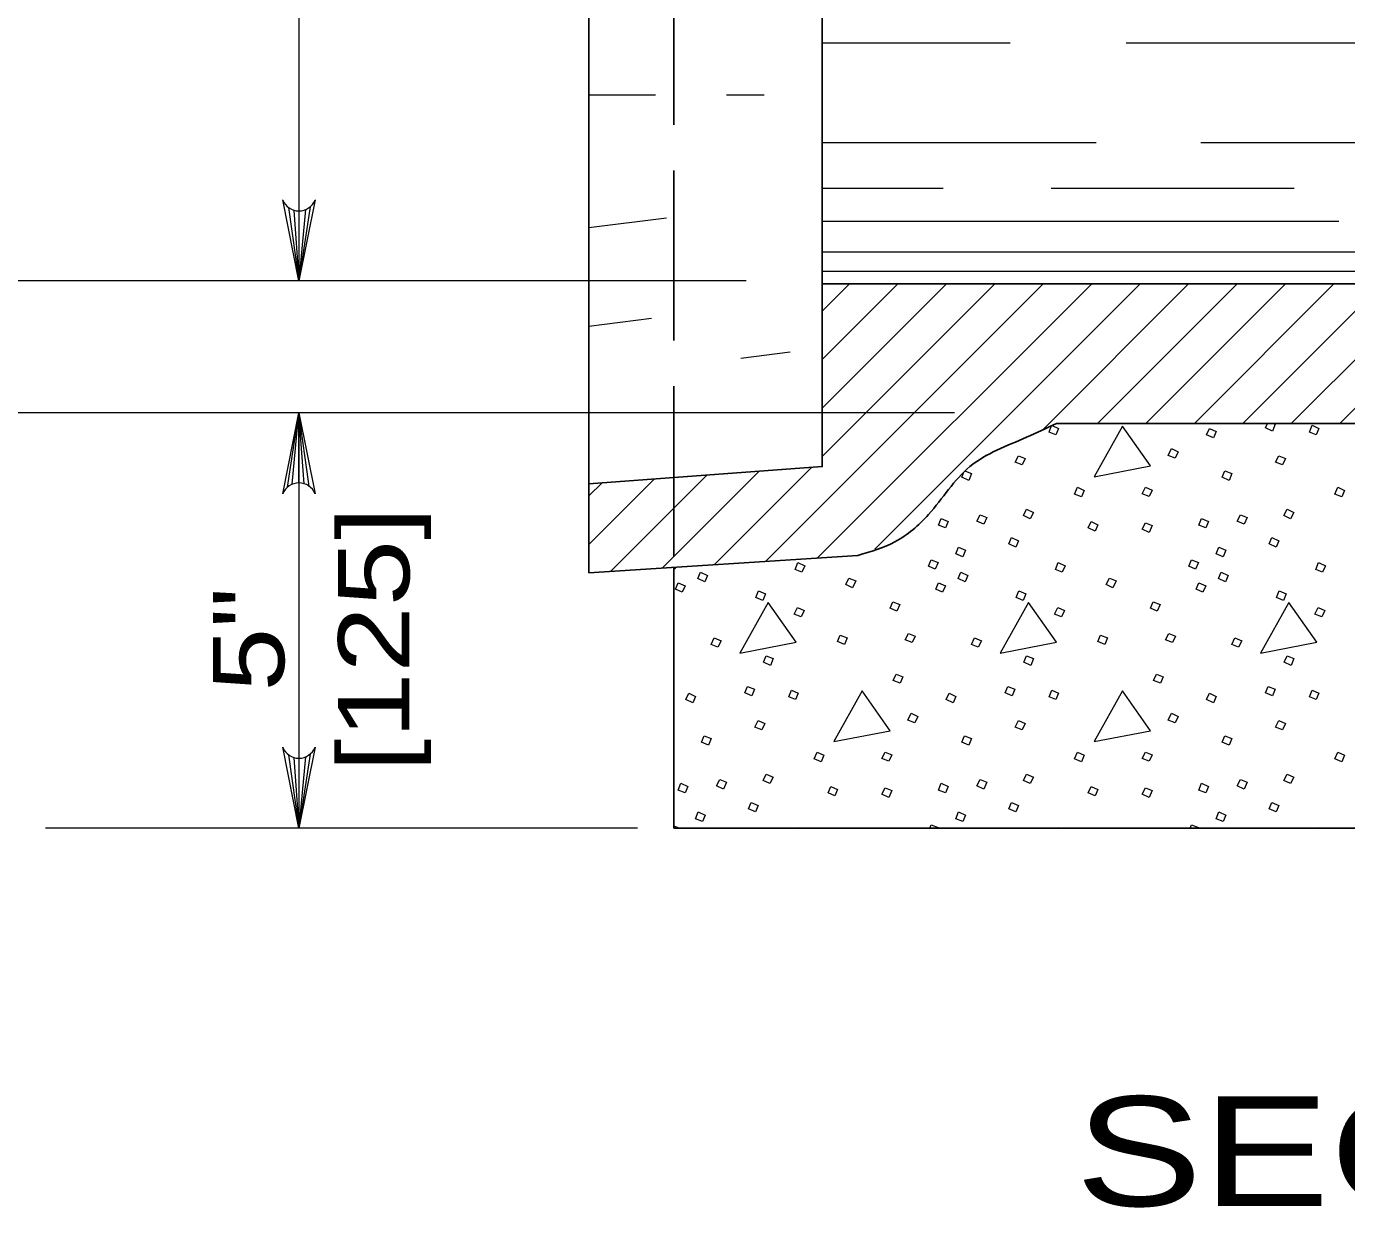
# Model space of a CAD drawing. Extents: x 1036.7 to 1070.7, y 883.9 to 905.9.
# Drawn here: x 1056.851 to 1059.74, y 892.979 to 895.565 of the extents above; entities that cross this region are included whole.
import ezdxf
from ezdxf.enums import TextEntityAlignment as Align

# ---------------------------------------------------------------- set-up
doc = ezdxf.new("R2010")
doc.units = 0
doc.header["$LTSCALE"] = 0.062
doc.linetypes.add('LONG_DASHED', pattern=[7.5, 6, -1.5])
doc.layers.add('1', color=7, linetype='Continuous', lineweight=13)

msp = doc.modelspace()

# ---------------------------------------------------------------- linework, layer by layer
at = {"layer": '1', "lineweight": 25}
for p, q in [((1058.08233, 898.76567), (1058.08233, 894.5635)), ((1058.59283, 898.16642), (1058.59283, 894.9815)), ((1062.80458, 895.00108), (1058.59283, 895.00108)), ((1062.80458, 894.69575), (1059.10533, 894.69575)), ((1058.67108, 894.407), (1058.08233, 894.36883)), ((1058.26842, 894.38092), (1058.26842, 893.80992))]:
    msp.add_line(p, q, dxfattribs=at)
at = {"layer": '1', "linetype": 'LONG_DASHED', "lineweight": 25}
msp.add_line((1058.26842, 898.55342), (1058.26842, 894.38092), dxfattribs=at)
at = {"layer": '1'}
for p, q in [((1057.4475, 895.8775), (1057.4475, 895.00783)), ((1058.59283, 895.52883), (1059.00425, 895.52883)), ((1059.25767, 895.52883), (1059.82158, 895.52883)), ((1058.08233, 895.41525), (1058.228, 895.41525)), ((1058.383, 895.41525), (1058.46592, 895.41525)), ((1058.59283, 895.31058), (1059.19225, 895.31058)), ((1059.42108, 895.31058), (1060.05858, 895.31058)), ((1058.59283, 895.21083), (1058.85717, 895.21083)), ((1059.09417, 895.21083), (1059.62542, 895.21083)), ((1057.42508, 895.168), (1057.4475, 895.00783)), ((1057.43617, 895.16258), (1057.4475, 895.00783)), ((1057.47225, 895.16992), (1057.4475, 895.00783)), ((1057.46192, 895.16383), (1057.4475, 895.00783)), ((1057.4475, 895.161), (1057.4475, 895.00783)), ((1058.08233, 895.12425), (1058.25175, 895.14592)), ((1058.59283, 895.13858), (1059.7235, 895.13858)), ((1058.59283, 895.07167), (1062.80458, 895.07167)), ((1058.42608, 895.00783), (1054.42967, 895.00783)), ((1058.59283, 895.029), (1062.80458, 895.029)), ((1058.46933, 894.39392), (1059.07658, 895.00108)), ((1058.58275, 894.40125), (1059.18258, 895.00108)), ((1058.59283, 894.94133), (1058.6525, 895.00108)), ((1058.59283, 894.83533), (1058.75858, 895.00108)), ((1058.59283, 894.72942), (1058.8645, 895.00108)), ((1058.59283, 894.62333), (1058.97058, 895.00108)), ((1058.708, 894.4205), (1059.28867, 895.00108)), ((1059.07542, 894.68192), (1059.39458, 895.00108)), ((1059.19525, 894.69575), (1059.50067, 895.00108)), ((1059.30133, 894.69575), (1059.60667, 895.00108)), ((1059.40733, 894.69575), (1059.71267, 895.00108)), ((1059.51333, 894.69575), (1059.81875, 895.00108)), ((1059.61933, 894.69575), (1059.92467, 895.00108)), ((1059.72533, 894.69575), (1060.03075, 895.00108)), ((1058.08233, 894.90883), (1058.21942, 894.92633)), ((1058.4145, 894.83842), (1058.52233, 894.85217)), ((1058.88267, 894.71867), (1054.302, 894.71867)), ((1057.42275, 894.5565), (1057.4475, 894.71867)), ((1057.43308, 894.56267), (1057.4475, 894.71867)), ((1057.4475, 894.5655), (1057.4475, 894.71867)), ((1057.45883, 894.56383), (1057.4475, 894.71867)), ((1057.46992, 894.55842), (1057.4475, 894.71867)), ((1058.08233, 894.43092), (1058.22558, 894.57417)), ((1058.12925, 894.37192), (1058.34, 894.58267)), ((1058.24267, 894.37925), (1058.4545, 894.59108)), ((1058.356, 894.38658), (1058.56908, 894.59958)), ((1058.08233, 894.53692), (1058.111, 894.56567)), ((1058.08233, 894.36883), (1058.26842, 894.38092)), ((1057.42508, 893.97017), (1057.4475, 893.80992)), ((1057.43617, 893.96475), (1057.4475, 893.80992)), ((1057.47225, 893.972), (1057.4475, 893.80992)), ((1057.46192, 893.96592), (1057.4475, 893.80992)), ((1057.4475, 893.96308), (1057.4475, 893.80992)), ((1058.1885, 893.80992), (1056.89267, 893.80992)), ((1058.53892, 893.80992), (1058.5395, 893.81142)), ((1058.5395, 893.81142), (1058.54275, 893.80992)), ((1058.82808, 893.80992), (1058.83133, 893.81742)), ((1059.10867, 893.80992), (1059.10925, 893.81142)), ((1059.10925, 893.81142), (1059.1125, 893.80992)), ((1059.39783, 893.80992), (1059.40108, 893.81742)), ((1059.67833, 893.80992), (1059.679, 893.81142)), ((1059.679, 893.81142), (1059.68217, 893.80992))]:
    msp.add_line(p, q, dxfattribs=at)
for points in [[(1057.48292, 895.18483), (1057.4475, 895.00783), (1057.41208, 895.18483)], [(1057.41208, 894.54167), (1057.4475, 894.71867), (1057.48292, 894.54167)], [(1057.4475, 894.71867), (1057.4475, 894.10808), (1057.4475, 893.80992)], [(1059.09617, 894.6915), (1059.11025, 894.68492), (1059.10425, 894.67092), (1059.08925, 894.67692), (1059.09483, 894.69092)], [(1059.57942, 894.69575), (1059.584, 894.69392), (1059.578, 894.67892), (1059.563, 894.68592), (1059.56725, 894.69575)], [(1058.90633, 894.59108), (1058.91933, 894.586), (1058.91333, 894.571), (1058.89833, 894.578), (1058.90208, 894.58658)], [(1058.27233, 894.38117), (1058.27058, 894.37708), (1058.26842, 894.37792)], [(1057.48292, 893.98692), (1057.4475, 893.80992), (1057.41208, 893.98692)], [(1058.26842, 893.81467), (1058.27658, 893.81142), (1058.27592, 893.80992)], [(1058.83133, 893.81742), (1058.84633, 893.81142), (1058.84567, 893.80992)], [(1059.40108, 893.81742), (1059.41608, 893.81142), (1059.41542, 893.80992)]]:
    msp.add_lwpolyline(points, dxfattribs=at)
at = {"layer": '1', "lineweight": 25}
for points in [[(1058.59283, 894.9815), (1058.59283, 894.60133), (1058.08233, 894.5635), (1058.08233, 894.36883)], [(1058.26842, 893.80992), (1061.4155, 893.80992), (1062.48425, 893.80992)]]:
    msp.add_lwpolyline(points, dxfattribs=at)
at = {"layer": '1'}
for points in [[(1059.25017, 894.68992), (1059.18817, 894.579), (1059.31117, 894.60292)], [(1059.665, 894.69192), (1059.68, 894.68492), (1059.674, 894.67092), (1059.659, 894.67692)], [(1059.44008, 894.68492), (1059.45508, 894.67792), (1059.44908, 894.66392), (1059.43408, 894.67092)], [(1059.35708, 894.64092), (1059.37208, 894.63392), (1059.36508, 894.61992), (1059.35008, 894.62592)], [(1059.02225, 894.62492), (1059.03725, 894.61892), (1059.03025, 894.60492), (1059.01525, 894.61092)], [(1059.592, 894.62492), (1059.607, 894.61892), (1059.6, 894.60492), (1059.585, 894.61092)], [(1059.47408, 894.59192), (1059.48908, 894.586), (1059.48308, 894.571), (1059.46808, 894.578)], [(1059.15117, 894.556), (1059.16617, 894.549), (1059.16017, 894.535), (1059.14525, 894.541)], [(1059.30017, 894.556), (1059.31517, 894.55), (1059.30817, 894.536), (1059.29317, 894.542)], [(1059.72092, 894.556), (1059.73592, 894.549), (1059.72992, 894.535), (1059.71492, 894.541)], [(1058.85333, 894.488), (1058.86833, 894.481), (1058.86233, 894.467), (1058.84733, 894.473)], [(1058.93833, 894.496), (1058.95333, 894.49), (1058.94633, 894.475), (1058.93133, 894.482)], [(1059.04025, 894.508), (1059.05525, 894.501), (1059.04825, 894.487), (1059.03325, 894.494)], [(1059.42308, 894.488), (1059.43808, 894.481), (1059.43208, 894.467), (1059.41708, 894.473)], [(1059.508, 894.496), (1059.523, 894.49), (1059.516, 894.475), (1059.50108, 894.482)], [(1059.61, 894.508), (1059.625, 894.501), (1059.618, 894.487), (1059.603, 894.494)], [(1059.18117, 894.481), (1059.19617, 894.474), (1059.19017, 894.46), (1059.17517, 894.467)], [(1059.30017, 894.478), (1059.31517, 894.472), (1059.30817, 894.457), (1059.29317, 894.464)], [(1059.00725, 894.446), (1059.02225, 894.439), (1059.01625, 894.42508), (1059.00125, 894.43208)], [(1059.577, 894.446), (1059.592, 894.439), (1059.586, 894.42508), (1059.571, 894.43208)], [(1058.89133, 894.42508), (1058.90633, 894.41808), (1058.90033, 894.40408), (1058.88533, 894.41008)], [(1059.46108, 894.42508), (1059.47608, 894.41808), (1059.47008, 894.40408), (1059.45508, 894.41008)], [(1058.32658, 894.37008), (1058.34158, 894.36308), (1058.33558, 894.34908), (1058.32058, 894.35608)], [(1058.5395, 894.39108), (1058.5545, 894.38408), (1058.5485, 894.37008), (1058.5335, 894.37608)], [(1058.83133, 894.39708), (1058.84633, 894.39108), (1058.84033, 894.37708), (1058.82533, 894.38308)], [(1058.89633, 894.37008), (1058.91133, 894.36308), (1058.90533, 894.34908), (1058.89033, 894.35608)], [(1059.10925, 894.39108), (1059.12425, 894.38408), (1059.11825, 894.37008), (1059.10325, 894.37608)], [(1059.40108, 894.39708), (1059.41608, 894.39108), (1059.41008, 894.37708), (1059.39508, 894.38308)], [(1059.46608, 894.37008), (1059.48108, 894.36308), (1059.47508, 894.34908), (1059.46008, 894.35608)], [(1059.679, 894.39108), (1059.69392, 894.38408), (1059.68792, 894.37008), (1059.673, 894.37608)], [(1058.27758, 894.34708), (1058.29258, 894.34008), (1058.28658, 894.32608), (1058.27158, 894.33308)], [(1058.65142, 894.35708), (1058.66642, 894.35108), (1058.65942, 894.33608), (1058.64442, 894.34308)], [(1058.84733, 894.34708), (1058.86233, 894.34008), (1058.85633, 894.32608), (1058.84133, 894.33308)], [(1059.22117, 894.35708), (1059.23617, 894.35108), (1059.22917, 894.33608), (1059.21417, 894.34308)], [(1059.41708, 894.34708), (1059.43208, 894.34008), (1059.42608, 894.32608), (1059.41108, 894.33308)], [(1058.4535, 894.32908), (1058.4685, 894.32308), (1058.4625, 894.30808), (1058.4475, 894.31508)], [(1059.02325, 894.32908), (1059.03825, 894.32308), (1059.03225, 894.30808), (1059.01725, 894.31508)], [(1059.593, 894.32908), (1059.608, 894.32308), (1059.602, 894.30808), (1059.587, 894.31508)], [(1058.4745, 894.30408), (1058.41258, 894.19317), (1058.5355, 894.21717)], [(1058.5385, 894.29317), (1058.5535, 894.28617), (1058.5465, 894.27217), (1058.5315, 894.27817)], [(1058.74742, 894.30508), (1058.76242, 894.29908), (1058.75642, 894.28517), (1058.74142, 894.29117)], [(1059.04425, 894.30408), (1058.98225, 894.19317), (1059.10525, 894.21717)], [(1059.10825, 894.29317), (1059.12325, 894.28617), (1059.11625, 894.27217), (1059.10125, 894.27817)], [(1059.31717, 894.30508), (1059.33208, 894.29908), (1059.32608, 894.28517), (1059.31117, 894.29117)], [(1059.614, 894.30408), (1059.552, 894.19317), (1059.675, 894.21717)], [(1059.67792, 894.29317), (1059.69292, 894.28617), (1059.68592, 894.27217), (1059.671, 894.27817)], [(1058.35658, 894.22617), (1058.37158, 894.22017), (1058.36458, 894.20617), (1058.34958, 894.21217)], [(1058.63242, 894.23217), (1058.64742, 894.22617), (1058.64142, 894.21217), (1058.62642, 894.21817)], [(1058.78142, 894.23617), (1058.79642, 894.23017), (1058.78942, 894.21617), (1058.77442, 894.22217)], [(1058.92633, 894.22617), (1058.94133, 894.22017), (1058.93433, 894.20617), (1058.91933, 894.21217)], [(1059.20217, 894.23217), (1059.21717, 894.22617), (1059.21117, 894.21217), (1059.19617, 894.21817)], [(1059.35108, 894.23617), (1059.36608, 894.23017), (1059.35908, 894.21617), (1059.34408, 894.22217)], [(1059.49608, 894.22617), (1059.511, 894.22017), (1059.504, 894.20617), (1059.48908, 894.21217)], [(1058.4705, 894.18717), (1058.4855, 894.18117), (1058.4795, 894.16617), (1058.4645, 894.17317)], [(1059.04025, 894.18717), (1059.05525, 894.18117), (1059.04925, 894.16617), (1059.03425, 894.17317)], [(1059.61, 894.18717), (1059.625, 894.18117), (1059.619, 894.16617), (1059.604, 894.17317)], [(1058.75442, 894.14725), (1058.76942, 894.14125), (1058.76342, 894.12725), (1058.74842, 894.13325)], [(1059.32417, 894.14725), (1059.33908, 894.14125), (1059.33308, 894.12725), (1059.31817, 894.13325)], [(1058.42958, 894.12025), (1058.4445, 894.11425), (1058.43858, 894.09925), (1058.42358, 894.10625)], [(1058.5255, 894.11225), (1058.5405, 894.10525), (1058.5345, 894.09125), (1058.5195, 894.09725)], [(1058.68042, 894.11025), (1058.6185, 893.99933), (1058.74142, 894.02325)], [(1058.99925, 894.12025), (1059.01425, 894.11425), (1059.00825, 894.09925), (1058.99325, 894.10625)], [(1059.09525, 894.11225), (1059.11025, 894.10525), (1059.10425, 894.09125), (1059.08925, 894.09725)], [(1059.25017, 894.11025), (1059.18817, 893.99933), (1059.31117, 894.02325)], [(1059.569, 894.12025), (1059.584, 894.11425), (1059.578, 894.09925), (1059.563, 894.10625)], [(1059.665, 894.11225), (1059.68, 894.10525), (1059.674, 894.09125), (1059.659, 894.09725)], [(1058.30058, 894.10525), (1058.31558, 894.09825), (1058.30958, 894.08425), (1058.29458, 894.09125)], [(1058.87033, 894.10525), (1058.88533, 894.09825), (1058.87933, 894.08425), (1058.86433, 894.09125)], [(1059.44008, 894.10525), (1059.45508, 894.09825), (1059.44908, 894.08425), (1059.43408, 894.09125)], [(1058.78742, 894.06125), (1058.80233, 894.05425), (1058.79542, 894.04025), (1058.78042, 894.04625)], [(1059.35708, 894.06125), (1059.37208, 894.05425), (1059.36508, 894.04025), (1059.35008, 894.04625)], [(1058.4525, 894.04525), (1058.4675, 894.03925), (1058.4605, 894.02525), (1058.4455, 894.03125)], [(1059.02225, 894.04525), (1059.03725, 894.03925), (1059.03025, 894.02525), (1059.01525, 894.03125)], [(1059.592, 894.04525), (1059.607, 894.03925), (1059.6, 894.02525), (1059.585, 894.03125)], [(1058.33458, 894.01225), (1058.34958, 894.00633), (1058.34358, 893.99133), (1058.32858, 893.99833)], [(1058.90433, 894.01225), (1058.91933, 894.00633), (1058.91333, 893.99133), (1058.89833, 893.99833)], [(1059.47408, 894.01225), (1059.48908, 894.00633), (1059.48308, 893.99133), (1059.46808, 893.99833)], [(1058.5815, 893.97633), (1058.5965, 893.96933), (1058.5905, 893.95533), (1058.5755, 893.96133)], [(1058.73042, 893.97633), (1058.74542, 893.97033), (1058.73842, 893.95633), (1058.72342, 893.96233)], [(1059.15117, 893.97633), (1059.16617, 893.96933), (1059.16017, 893.95533), (1059.14525, 893.96133)], [(1059.30017, 893.97633), (1059.31517, 893.97033), (1059.30817, 893.95633), (1059.29317, 893.96233)], [(1059.72092, 893.97633), (1059.73592, 893.96933), (1059.72992, 893.95533), (1059.71492, 893.96133)], [(1058.28358, 893.90833), (1058.29858, 893.90133), (1058.29258, 893.88733), (1058.27758, 893.89333)], [(1058.36858, 893.91633), (1058.38358, 893.91033), (1058.37658, 893.89533), (1058.36158, 893.90233)], [(1058.4705, 893.92833), (1058.4855, 893.92133), (1058.4785, 893.90733), (1058.4635, 893.91433)], [(1058.85333, 893.90833), (1058.86833, 893.90133), (1058.86233, 893.88733), (1058.84733, 893.89333)], [(1058.93833, 893.91633), (1058.95333, 893.91033), (1058.94633, 893.89533), (1058.93133, 893.90233)], [(1059.04025, 893.92833), (1059.05525, 893.92133), (1059.04825, 893.90733), (1059.03325, 893.91433)], [(1059.42308, 893.90833), (1059.43808, 893.90133), (1059.43208, 893.88733), (1059.41708, 893.89333)], [(1059.508, 893.91633), (1059.523, 893.91033), (1059.516, 893.89533), (1059.50108, 893.90233)], [(1059.61, 893.92833), (1059.625, 893.92133), (1059.618, 893.90733), (1059.603, 893.91433)], [(1058.6115, 893.90133), (1058.62642, 893.89433), (1058.62042, 893.88033), (1058.6055, 893.88733)], [(1058.73042, 893.89833), (1058.74542, 893.89233), (1058.73842, 893.87733), (1058.72342, 893.88433)], [(1059.18117, 893.90133), (1059.19617, 893.89433), (1059.19017, 893.88033), (1059.17517, 893.88733)], [(1059.30017, 893.89833), (1059.31517, 893.89233), (1059.30817, 893.87733), (1059.29317, 893.88433)], [(1058.4375, 893.86633), (1058.4525, 893.85942), (1058.4465, 893.84542), (1058.43158, 893.85242)], [(1059.00725, 893.86633), (1059.02225, 893.85942), (1059.01625, 893.84542), (1059.00125, 893.85242)], [(1059.577, 893.86633), (1059.592, 893.85942), (1059.586, 893.84542), (1059.571, 893.85242)], [(1058.32158, 893.84542), (1058.33658, 893.83842), (1058.33058, 893.82442), (1058.31558, 893.83042)], [(1058.89133, 893.84542), (1058.90633, 893.83842), (1058.90033, 893.82442), (1058.88533, 893.83042)], [(1059.46108, 893.84542), (1059.47608, 893.83842), (1059.47008, 893.82442), (1059.45508, 893.83042)]]:
    msp.add_lwpolyline(points, close=True, dxfattribs=at)
for centre, start, end in [((1057.44747, 895.19909), 202.08782, 337.91395), ((1057.44755, 894.52734), 22.08782, 157.91395), ((1057.44747, 894.0012), 202.08782, 337.91395)]:
    msp.add_arc(centre, 0.0382, start, end, dxfattribs=at)
at = {"layer": '1', "lineweight": 25}
msp.add_spline([(1059.10533, 894.69575), (1059.04008, 894.6655), (1058.91608, 894.60125), (1058.82558, 894.49642), (1058.7515, 894.43642), (1058.67108, 894.407)], degree=3, dxfattribs=at)

# ---------------------------------------------------------------- texts
at = {"layer": '1'}
for s, width, p in [('[125]', 1.25, (1057.68942, 894.22308)), ('5"', 1.2, (1057.41542, 894.22312))]:
    msp.add_text(s, height=0.156, rotation=90, dxfattribs=dict(at, width=width)).set_placement(p, align=Align.CENTER)
at = {"layer": '1', "width": 1.3}
msp.add_text('SECTION D-D', height=0.24, dxfattribs=at).set_placement((1059.14658, 892.98283))

doc.saveas('drawing.dxf')
